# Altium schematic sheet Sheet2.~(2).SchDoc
size A
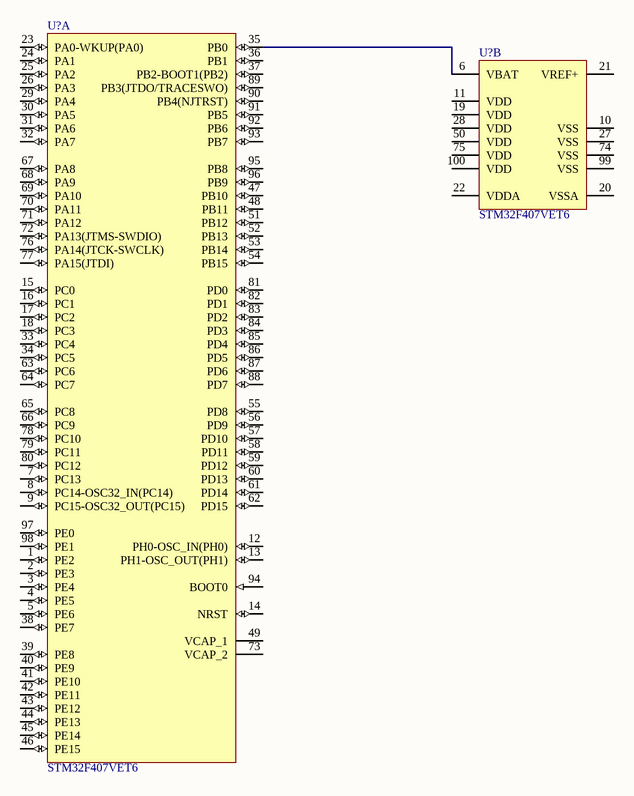
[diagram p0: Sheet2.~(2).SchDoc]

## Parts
(Parts that share a designator on the sheet are numbered #1, #2 ... from top to bottom, then left to right.)
U?#1  STM32F407VET6  [STM-LQFP100_M]  (part A of 2)
U?#2  STM32F407VET6  [STM-LQFP100_M]  (part B of 2)

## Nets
NetU?#1_35: U?#1.35(PB0) U?#2.6(VBAT)

Not connected (* = marked no-connect by the designer): U?#1 1(PE2) 2(PE3) 3(PE4) 4(PE5) 5(PE6) 7(PC13) 8(PC14-OSC32_IN(PC14)) 9(PC15-OSC32_OUT(PC15)) 12(PH0-OSC_IN(PH0)) 13(PH1-OSC_OUT(PH1)) 14(NRST) 15(PC0) 16(PC1) 17(PC2) 18(PC3) 23(PA0-WKUP(PA0)) 24(PA1) 25(PA2) 26(PA3) 29(PA4) 30(PA5) 31(PA6) 32(PA7) 33(PC4) 34(PC5) 36(PB1) 37(PB2-BOOT1(PB2)) 38(PE7) 39(PE8) 40(PE9) 41(PE10) 42(PE11) 43(PE12) 44(PE13) 45(PE14) 46(PE15) 47(PB10) 48(PB11) 49(VCAP_1) 51(PB12) 52(PB13) 53(PB14) 54(PB15) 55(PD8) 56(PD9) 57(PD10) 58(PD11) 59(PD12) 60(PD13) 61(PD14) 62(PD15) 63(PC6) 64(PC7) 65(PC8) 66(PC9) 67(PA8) 68(PA9) 69(PA10) 70(PA11) 71(PA12) 72(PA13(JTMS-SWDIO)) 73(VCAP_2) 76(PA14(JTCK-SWCLK)) 77(PA15(JTDI)) 78(PC10) 79(PC11) 80(PC12) 81(PD0) 82(PD1) 83(PD2) 84(PD3) 85(PD4) 86(PD5) 87(PD6) 88(PD7) 89(PB3(JTDO/TRACESWO)) 90(PB4(NJTRST)) 91(PB5) 92(PB6) 93(PB7) 94(BOOT0) 95(PB8) 96(PB9) 97(PE0) 98(PE1); U?#2 10(VSS) 11(VDD) 19(VDD) 20(VSSA) 21(VREF+) 22(VDDA) 27(VSS) 28(VDD) 50(VDD) 74(VSS) 75(VDD) 99(VSS) 100(VDD)

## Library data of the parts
U?#1 U?#2 = CMP-0243-00016-3: ARM Cortex-M4 32-bit MCU+FPU, 210 DMIPS, 512 kB Flash, 192 kB Internal RAM, 82 I/Os, 100-pin LQFP, -40 to 85 degC, Tray; Manufacturer: STMicroelectronics; Supply Voltage(Vcc) max (V): 3.6; Supply Voltage(Vcc) min (V): 1.8; I/Os (High Current): 82; FLASH Size (Prog) (kB): 512; Operating Frequency(F) (Processor speed) (MHz): 168; D/A Converter: 2x12-bit; Internal RAM Size (kB): 192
